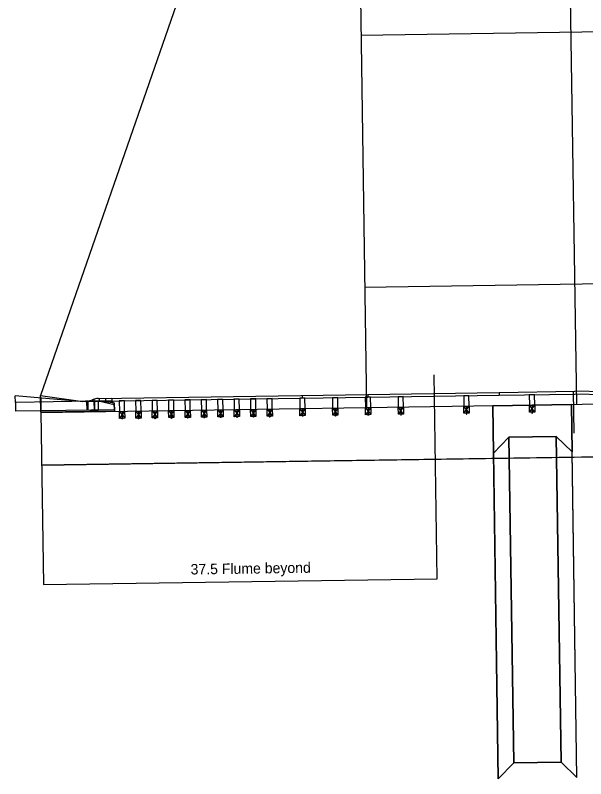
# Model space of a CAD drawing. Extents: x 17498307 to 17498862, y 7167523 to 7167641.
# Drawn here: x 17498671.2 to 17498725.6, y 7167525.4 to 7167598.2 of the extents above; entities that cross this region are included whole.
import ezdxf

# ---------------------------------------------------------------- set-up
doc = ezdxf.new("R2010")
doc.units = 0
for name, color, linetype in [('_CIVIL_CONSTRUCTION', 7, 'Continuous'), ('BridgeSuperStructure', 7, 'Continuous'), ('Default', 7, 'Continuous'), ('Draft_DNC', 7, 'Continuous'), ('dsnCellElements', 7, 'Continuous'), ('TextAlignment', 7, 'Continuous'), ('TL_ForeSlopeBarnRoof', 7, 'Continuous')]:
    doc.layers.add(name, color=color, linetype=linetype)

msp = doc.modelspace()

# ---------------------------------------------------------------- linework, layer by layer
at = {"layer": '_CIVIL_CONSTRUCTION'}
for p, q in [((17498703.967, 7167607.973), (17498704.671, 7167560.765)), ((17498723.964, 7167608.272), (17498724.669, 7167561.067)), ((17498688.995, 7167606.167), (17498673.635, 7167561.932)), ((17498704.142, 7167596.251), (17498754.136, 7167596.997)), ((17498704.5, 7167572.256), (17498754.494, 7167573.003)), ((17498732.925, 7167561.192), (17498673.66, 7167560.296))]:
    msp.add_line(p, q, dxfattribs=at)
at = {"layer": 'BridgeSuperStructure'}
msp.add_line((17498671.219, 7167561.896), (17498671.219, 7167561.896), dxfattribs=at)
at = {"layer": 'Default'}
msp.add_line((17498724.356, 7167562.344), (17498724.419, 7167558.345), dxfattribs=at)
for points in [[(17498680.646, 7167561.245), (17498680.658, 7167560.453), (17498673.659, 7167560.349), (17498673.635, 7167561.932), (17498677.644, 7167561.367), (17498679.644, 7167561.397)], [(17498716.763, 7167556.459), (17498716.696, 7167560.959), (17498724.195, 7167561.071), (17498724.262, 7167556.571), (17498722.74, 7167558.049), (17498718.241, 7167557.981)]]:
    msp.add_lwpolyline(points, close=True, dxfattribs=at)
at = {"layer": 'Draft_DNC'}
for p, q in [((17498711.401, 7167544.493), (17498711.111, 7167563.921)), ((17498673.659, 7167560.349), (17498673.904, 7167543.934)), ((17498732.9, 7167556.191), (17498673.735, 7167555.296)), ((17498673.904, 7167543.934), (17498711.401, 7167544.493))]:
    msp.add_line(p, q, dxfattribs=at)
at = {"layer": 'dsnCellElements'}
for p, q in [((17498671.228, 7167561.282), (17498671.219, 7167561.896)), ((17498677.394, 7167561.374), (17498671.219, 7167561.896)), ((17498679.202, 7167561.672), (17498704.803, 7167562.053)), ((17498698.554, 7167561.96), (17498698.558, 7167561.689)), ((17498704.803, 7167562.053), (17498717.302, 7167562.24)), ((17498704.803, 7167562.053), (17498704.808, 7167561.783)), ((17498704.808, 7167561.783), (17498717.306, 7167561.969)), ((17498708.183, 7167561.833), (17498707.682, 7167561.826)), ((17498708.197, 7167560.832), (17498708.183, 7167561.833)), ((17498714.432, 7167561.926), (17498713.932, 7167561.919)), ((17498713.932, 7167561.919), (17498713.946, 7167560.918)), ((17498714.447, 7167560.926), (17498714.432, 7167561.926)), ((17498717.302, 7167562.24), (17498717.306, 7167561.969)), ((17498678.415, 7167561.389), (17498671.228, 7167561.282)), ((17498671.228, 7167561.282), (17498671.241, 7167560.438)), ((17498673.639, 7167561.691), (17498673.657, 7167560.474)), ((17498678.164, 7167561.411), (17498677.914, 7167561.407)), ((17498677.915, 7167561.382), (17498677.914, 7167561.407)), ((17498677.915, 7167561.382), (17498680.415, 7167561.419)), ((17498678.052, 7167560.54), (17498678.04, 7167561.383)), ((17498678.093, 7167560.593), (17498678.081, 7167561.411)), ((17498678.123, 7167561.385), (17498678.136, 7167560.541)), ((17498679.144, 7167561.4), (17498678.415, 7167561.389)), ((17498678.645, 7167561.57), (17498678.503, 7167561.512)), ((17498678.706, 7167561.393), (17498678.719, 7167560.55)), ((17498678.76, 7167560.603), (17498678.745, 7167561.605)), ((17498678.802, 7167560.551), (17498678.79, 7167561.395)), ((17498679.106, 7167561.67), (17498680.411, 7167561.69)), ((17498680.31, 7167561.417), (17498679.144, 7167561.4)), ((17498680.649, 7167561.047), (17498679.144, 7167561.4)), ((17498679.156, 7167560.556), (17498679.144, 7167561.4)), ((17498679.202, 7167561.672), (17498679.206, 7167561.401)), ((17498679.206, 7167561.401), (17498704.808, 7167561.783)), ((17498679.411, 7167561.405), (17498680.415, 7167561.42)), ((17498679.806, 7167561.681), (17498679.81, 7167561.41)), ((17498680.647, 7167561.172), (17498680.31, 7167561.417)), ((17498680.411, 7167561.69), (17498680.415, 7167561.419)), ((17498680.656, 7167560.578), (17498680.647, 7167561.172)), ((17498681.623, 7167561.435), (17498681.123, 7167561.428)), ((17498681.123, 7167561.428), (17498681.138, 7167560.428)), ((17498681.638, 7167560.436), (17498681.623, 7167561.435)), ((17498683.185, 7167561.458), (17498682.685, 7167561.451)), ((17498682.685, 7167561.451), (17498682.7, 7167560.451)), ((17498683.2, 7167560.459), (17498683.185, 7167561.458)), ((17498684.747, 7167561.482), (17498684.248, 7167561.474)), ((17498684.248, 7167561.474), (17498684.263, 7167560.475)), ((17498684.762, 7167560.482), (17498684.747, 7167561.482)), ((17498686.31, 7167561.505), (17498685.81, 7167561.497)), ((17498685.81, 7167561.497), (17498685.825, 7167560.498)), ((17498686.325, 7167560.506), (17498686.31, 7167561.505)), ((17498687.872, 7167561.528), (17498687.372, 7167561.521)), ((17498687.372, 7167561.521), (17498687.387, 7167560.521)), ((17498687.887, 7167560.529), (17498687.872, 7167561.528)), ((17498689.434, 7167561.552), (17498688.935, 7167561.544)), ((17498688.935, 7167561.544), (17498688.95, 7167560.545)), ((17498689.449, 7167560.552), (17498689.434, 7167561.552)), ((17498690.997, 7167561.575), (17498690.497, 7167561.567)), ((17498690.497, 7167561.567), (17498690.512, 7167560.568)), ((17498691.012, 7167560.576), (17498690.997, 7167561.575)), ((17498692.559, 7167561.598), (17498692.059, 7167561.591)), ((17498692.559, 7167561.598), (17498692.059, 7167561.591)), ((17498692.059, 7167561.591), (17498692.074, 7167560.591)), ((17498692.059, 7167561.591), (17498692.074, 7167560.591)), ((17498692.574, 7167560.599), (17498692.559, 7167561.598)), ((17498692.574, 7167560.599), (17498692.559, 7167561.598)), ((17498694.121, 7167561.622), (17498693.622, 7167561.614)), ((17498693.622, 7167561.614), (17498693.636, 7167560.615)), ((17498694.136, 7167560.622), (17498694.121, 7167561.622)), ((17498695.684, 7167561.645), (17498695.184, 7167561.637)), ((17498695.184, 7167561.637), (17498695.199, 7167560.638)), ((17498695.698, 7167560.645), (17498695.684, 7167561.645)), ((17498698.808, 7167561.692), (17498698.309, 7167561.684)), ((17498698.309, 7167561.684), (17498698.323, 7167560.685)), ((17498698.823, 7167560.692), (17498698.808, 7167561.692)), ((17498701.933, 7167561.738), (17498701.433, 7167561.731)), ((17498701.433, 7167561.731), (17498701.448, 7167560.731)), ((17498701.948, 7167560.739), (17498701.933, 7167561.738)), ((17498705.058, 7167561.785), (17498704.558, 7167561.777)), ((17498704.558, 7167561.777), (17498704.573, 7167560.778)), ((17498705.072, 7167560.785), (17498705.058, 7167561.785)), ((17498707.682, 7167561.826), (17498707.697, 7167560.825)), ((17498678.427, 7167560.545), (17498671.241, 7167560.438)), ((17498679.156, 7167560.556), (17498678.427, 7167560.545)), ((17498680.656, 7167560.578), (17498679.156, 7167560.556)), ((17498681.138, 7167560.428), (17498681.638, 7167560.436)), ((17498681.138, 7167560.428), (17498681.648, 7167559.769)), ((17498681.638, 7167560.436), (17498681.148, 7167559.762)), ((17498681.388, 7167560.432), (17498681.398, 7167559.765)), ((17498682.7, 7167560.451), (17498683.2, 7167560.459)), ((17498682.7, 7167560.451), (17498683.21, 7167559.792)), ((17498683.2, 7167560.459), (17498682.71, 7167559.785)), ((17498682.95, 7167560.455), (17498682.96, 7167559.789)), ((17498684.262, 7167560.475), (17498684.772, 7167559.816)), ((17498684.263, 7167560.475), (17498684.762, 7167560.482)), ((17498684.762, 7167560.482), (17498684.272, 7167559.808)), ((17498684.512, 7167560.479), (17498684.522, 7167559.812)), ((17498685.825, 7167560.498), (17498686.325, 7167560.506)), ((17498685.825, 7167560.498), (17498686.335, 7167559.839)), ((17498686.325, 7167560.506), (17498685.835, 7167559.832)), ((17498686.075, 7167560.502), (17498686.085, 7167559.835)), ((17498687.387, 7167560.521), (17498687.887, 7167560.529)), ((17498687.387, 7167560.521), (17498687.897, 7167559.862)), ((17498687.887, 7167560.529), (17498687.397, 7167559.855)), ((17498687.637, 7167560.525), (17498687.647, 7167559.859)), ((17498688.949, 7167560.545), (17498689.459, 7167559.886)), ((17498688.95, 7167560.545), (17498689.449, 7167560.552)), ((17498689.449, 7167560.552), (17498688.959, 7167559.878)), ((17498689.199, 7167560.548), (17498689.209, 7167559.882)), ((17498690.512, 7167560.568), (17498691.012, 7167560.576)), ((17498690.512, 7167560.568), (17498691.021, 7167559.909)), ((17498691.012, 7167560.576), (17498690.522, 7167559.902)), ((17498690.762, 7167560.572), (17498690.771, 7167559.905)), ((17498692.074, 7167560.591), (17498692.574, 7167560.599)), ((17498692.074, 7167560.591), (17498692.574, 7167560.599)), ((17498692.074, 7167560.591), (17498692.584, 7167559.932)), ((17498692.574, 7167560.599), (17498692.084, 7167559.925)), ((17498692.324, 7167560.595), (17498692.334, 7167559.929)), ((17498693.636, 7167560.615), (17498694.136, 7167560.622)), ((17498693.636, 7167560.615), (17498694.146, 7167559.956)), ((17498694.136, 7167560.622), (17498693.646, 7167559.948)), ((17498693.886, 7167560.618), (17498693.896, 7167559.952)), ((17498695.199, 7167560.638), (17498695.698, 7167560.645)), ((17498695.199, 7167560.638), (17498695.708, 7167559.979)), ((17498695.698, 7167560.645), (17498695.208, 7167559.971)), ((17498695.449, 7167560.642), (17498695.458, 7167559.975)), ((17498698.323, 7167560.685), (17498698.823, 7167560.692)), ((17498698.323, 7167560.685), (17498698.833, 7167560.026)), ((17498698.823, 7167560.692), (17498698.333, 7167560.018)), ((17498698.573, 7167560.688), (17498698.583, 7167560.022)), ((17498701.448, 7167560.731), (17498701.948, 7167560.739)), ((17498701.448, 7167560.731), (17498701.958, 7167560.072)), ((17498701.948, 7167560.739), (17498701.458, 7167560.065)), ((17498701.698, 7167560.735), (17498701.708, 7167560.069)), ((17498704.572, 7167560.778), (17498705.082, 7167560.119)), ((17498704.573, 7167560.778), (17498705.072, 7167560.785)), ((17498705.072, 7167560.785), (17498704.582, 7167560.111)), ((17498704.822, 7167560.782), (17498704.832, 7167560.115)), ((17498707.697, 7167560.825), (17498708.197, 7167560.832)), ((17498708.207, 7167560.166), (17498707.697, 7167560.825)), ((17498707.707, 7167560.158), (17498708.197, 7167560.832)), ((17498707.947, 7167560.829), (17498707.957, 7167560.162)), ((17498713.946, 7167560.918), (17498714.447, 7167560.926)), ((17498714.456, 7167560.259), (17498713.946, 7167560.918)), ((17498713.956, 7167560.252), (17498714.446, 7167560.926)), ((17498714.196, 7167560.922), (17498714.206, 7167560.255)), ((17498724.195, 7167561.071), (17498716.696, 7167560.959)), ((17498717.226, 7167525.445), (17498716.696, 7167560.959)), ((17498724.725, 7167525.557), (17498724.195, 7167561.071)), ((17498681.648, 7167559.769), (17498681.148, 7167559.762)), ((17498681.318, 7167559.764), (17498681.318, 7167559.748)), ((17498681.478, 7167559.75), (17498681.318, 7167559.748)), ((17498681.358, 7167559.748), (17498681.358, 7167559.711)), ((17498681.438, 7167559.712), (17498681.358, 7167559.711)), ((17498681.374, 7167559.748), (17498681.374, 7167559.711)), ((17498681.388, 7167559.711), (17498681.389, 7167559.682)), ((17498681.409, 7167559.682), (17498681.389, 7167559.682)), ((17498681.408, 7167559.712), (17498681.409, 7167559.682)), ((17498681.422, 7167559.749), (17498681.422, 7167559.712)), ((17498681.438, 7167559.749), (17498681.438, 7167559.712)), ((17498681.478, 7167559.767), (17498681.478, 7167559.75)), ((17498683.21, 7167559.792), (17498682.71, 7167559.785)), ((17498682.88, 7167559.787), (17498682.88, 7167559.771)), ((17498683.04, 7167559.773), (17498682.88, 7167559.771)), ((17498682.92, 7167559.772), (17498682.921, 7167559.734)), ((17498683.001, 7167559.735), (17498682.921, 7167559.734)), ((17498682.936, 7167559.772), (17498682.937, 7167559.734)), ((17498682.951, 7167559.735), (17498682.951, 7167559.705)), ((17498682.971, 7167559.705), (17498682.951, 7167559.705)), ((17498682.971, 7167559.735), (17498682.971, 7167559.705)), ((17498682.984, 7167559.772), (17498682.985, 7167559.735)), ((17498683, 7167559.773), (17498683.001, 7167559.735)), ((17498683.04, 7167559.79), (17498683.04, 7167559.773)), ((17498684.772, 7167559.816), (17498684.272, 7167559.808)), ((17498684.442, 7167559.811), (17498684.442, 7167559.794)), ((17498684.602, 7167559.797), (17498684.442, 7167559.794)), ((17498684.482, 7167559.795), (17498684.483, 7167559.757)), ((17498684.563, 7167559.759), (17498684.483, 7167559.757)), ((17498684.498, 7167559.795), (17498684.499, 7167559.758)), ((17498684.513, 7167559.758), (17498684.513, 7167559.728)), ((17498684.533, 7167559.729), (17498684.513, 7167559.728)), ((17498684.533, 7167559.758), (17498684.533, 7167559.729)), ((17498684.546, 7167559.796), (17498684.547, 7167559.758)), ((17498684.562, 7167559.796), (17498684.563, 7167559.759)), ((17498684.602, 7167559.813), (17498684.602, 7167559.797)), ((17498686.335, 7167559.839), (17498685.835, 7167559.832)), ((17498686.005, 7167559.834), (17498686.005, 7167559.818)), ((17498686.165, 7167559.82), (17498686.005, 7167559.818)), ((17498686.045, 7167559.818), (17498686.045, 7167559.781)), ((17498686.125, 7167559.782), (17498686.045, 7167559.781)), ((17498686.061, 7167559.818), (17498686.061, 7167559.781)), ((17498686.075, 7167559.781), (17498686.076, 7167559.752)), ((17498686.096, 7167559.752), (17498686.076, 7167559.752)), ((17498686.095, 7167559.782), (17498686.096, 7167559.752)), ((17498686.109, 7167559.819), (17498686.109, 7167559.782)), ((17498686.125, 7167559.819), (17498686.125, 7167559.782)), ((17498686.165, 7167559.836), (17498686.165, 7167559.82)), ((17498687.897, 7167559.862), (17498687.397, 7167559.855)), ((17498687.567, 7167559.857), (17498687.567, 7167559.841)), ((17498687.727, 7167559.843), (17498687.567, 7167559.841)), ((17498687.607, 7167559.841), (17498687.608, 7167559.804)), ((17498687.688, 7167559.805), (17498687.608, 7167559.804)), ((17498687.623, 7167559.842), (17498687.624, 7167559.804)), ((17498687.638, 7167559.805), (17498687.638, 7167559.775)), ((17498687.658, 7167559.775), (17498687.638, 7167559.775)), ((17498687.658, 7167559.805), (17498687.658, 7167559.775)), ((17498687.671, 7167559.842), (17498687.672, 7167559.805)), ((17498687.687, 7167559.843), (17498687.688, 7167559.805)), ((17498687.727, 7167559.86), (17498687.727, 7167559.843)), ((17498689.459, 7167559.886), (17498688.959, 7167559.878)), ((17498689.129, 7167559.881), (17498689.129, 7167559.864)), ((17498689.289, 7167559.867), (17498689.129, 7167559.864)), ((17498689.169, 7167559.865), (17498689.17, 7167559.827)), ((17498689.25, 7167559.829), (17498689.17, 7167559.827)), ((17498689.185, 7167559.865), (17498689.186, 7167559.828)), ((17498689.2, 7167559.828), (17498689.2, 7167559.798)), ((17498689.22, 7167559.799), (17498689.2, 7167559.798)), ((17498689.22, 7167559.828), (17498689.22, 7167559.799)), ((17498689.233, 7167559.866), (17498689.234, 7167559.828)), ((17498689.249, 7167559.866), (17498689.25, 7167559.829)), ((17498689.289, 7167559.883), (17498689.289, 7167559.867)), ((17498691.021, 7167559.909), (17498690.522, 7167559.902)), ((17498690.692, 7167559.904), (17498690.692, 7167559.888)), ((17498690.852, 7167559.89), (17498690.692, 7167559.888)), ((17498690.732, 7167559.888), (17498690.732, 7167559.851)), ((17498690.812, 7167559.852), (17498690.732, 7167559.851)), ((17498690.748, 7167559.888), (17498690.748, 7167559.851)), ((17498690.762, 7167559.851), (17498690.763, 7167559.822)), ((17498690.783, 7167559.822), (17498690.763, 7167559.822)), ((17498690.782, 7167559.851), (17498690.783, 7167559.822)), ((17498690.796, 7167559.889), (17498690.796, 7167559.852)), ((17498690.812, 7167559.889), (17498690.812, 7167559.852)), ((17498690.851, 7167559.906), (17498690.852, 7167559.89)), ((17498692.584, 7167559.932), (17498692.084, 7167559.925)), ((17498692.254, 7167559.927), (17498692.254, 7167559.911)), ((17498692.414, 7167559.913), (17498692.254, 7167559.911)), ((17498692.294, 7167559.911), (17498692.295, 7167559.874)), ((17498692.375, 7167559.875), (17498692.295, 7167559.874)), ((17498692.31, 7167559.912), (17498692.311, 7167559.874)), ((17498692.325, 7167559.874), (17498692.325, 7167559.845)), ((17498692.345, 7167559.845), (17498692.325, 7167559.845)), ((17498692.345, 7167559.875), (17498692.345, 7167559.845)), ((17498692.358, 7167559.912), (17498692.359, 7167559.875)), ((17498692.374, 7167559.913), (17498692.375, 7167559.875)), ((17498692.414, 7167559.93), (17498692.414, 7167559.913)), ((17498694.146, 7167559.956), (17498693.646, 7167559.948)), ((17498693.816, 7167559.951), (17498693.816, 7167559.934)), ((17498693.976, 7167559.937), (17498693.816, 7167559.934)), ((17498693.856, 7167559.935), (17498693.857, 7167559.897)), ((17498693.937, 7167559.899), (17498693.857, 7167559.897)), ((17498693.872, 7167559.935), (17498693.873, 7167559.898)), ((17498693.887, 7167559.898), (17498693.887, 7167559.868)), ((17498693.907, 7167559.869), (17498693.887, 7167559.868)), ((17498693.907, 7167559.898), (17498693.907, 7167559.869)), ((17498693.92, 7167559.936), (17498693.921, 7167559.898)), ((17498693.936, 7167559.936), (17498693.937, 7167559.899)), ((17498693.976, 7167559.953), (17498693.976, 7167559.937)), ((17498695.708, 7167559.979), (17498695.208, 7167559.971)), ((17498695.378, 7167559.974), (17498695.379, 7167559.957)), ((17498695.539, 7167559.96), (17498695.379, 7167559.957)), ((17498695.419, 7167559.958), (17498695.419, 7167559.921)), ((17498695.499, 7167559.922), (17498695.419, 7167559.921)), ((17498695.435, 7167559.958), (17498695.435, 7167559.921)), ((17498695.449, 7167559.921), (17498695.45, 7167559.892)), ((17498695.47, 7167559.892), (17498695.45, 7167559.892)), ((17498695.469, 7167559.921), (17498695.47, 7167559.892)), ((17498695.483, 7167559.959), (17498695.483, 7167559.922)), ((17498695.499, 7167559.959), (17498695.499, 7167559.922)), ((17498695.538, 7167559.976), (17498695.539, 7167559.96)), ((17498698.833, 7167560.026), (17498698.333, 7167560.018)), ((17498698.503, 7167560.021), (17498698.503, 7167560.004)), ((17498698.663, 7167560.007), (17498698.503, 7167560.004)), ((17498698.543, 7167560.005), (17498698.544, 7167559.967)), ((17498698.624, 7167559.969), (17498698.544, 7167559.967)), ((17498698.559, 7167560.005), (17498698.56, 7167559.968)), ((17498698.574, 7167559.968), (17498698.574, 7167559.938)), ((17498698.594, 7167559.939), (17498698.574, 7167559.938)), ((17498698.594, 7167559.968), (17498698.594, 7167559.939)), ((17498698.607, 7167560.006), (17498698.608, 7167559.968)), ((17498698.623, 7167560.006), (17498698.624, 7167559.969)), ((17498698.663, 7167560.023), (17498698.663, 7167560.007)), ((17498701.958, 7167560.072), (17498701.458, 7167560.065)), ((17498701.628, 7167560.067), (17498701.628, 7167560.051)), ((17498701.788, 7167560.053), (17498701.628, 7167560.051)), ((17498701.668, 7167560.051), (17498701.669, 7167560.014)), ((17498701.749, 7167560.015), (17498701.669, 7167560.014)), ((17498701.684, 7167560.052), (17498701.685, 7167560.014)), ((17498701.699, 7167560.014), (17498701.699, 7167559.985)), ((17498701.719, 7167559.985), (17498701.699, 7167559.985)), ((17498701.719, 7167560.015), (17498701.719, 7167559.985)), ((17498701.732, 7167560.052), (17498701.733, 7167560.015)), ((17498701.748, 7167560.053), (17498701.749, 7167560.015)), ((17498701.788, 7167560.07), (17498701.788, 7167560.053)), ((17498705.082, 7167560.119), (17498704.582, 7167560.111)), ((17498704.752, 7167560.114), (17498704.753, 7167560.097)), ((17498704.913, 7167560.1), (17498704.753, 7167560.097)), ((17498704.793, 7167560.098), (17498704.793, 7167560.061)), ((17498704.873, 7167560.062), (17498704.793, 7167560.061)), ((17498704.809, 7167560.098), (17498704.809, 7167560.061)), ((17498704.823, 7167560.061), (17498704.824, 7167560.032)), ((17498704.844, 7167560.032), (17498704.824, 7167560.032)), ((17498704.843, 7167560.061), (17498704.844, 7167560.032)), ((17498704.857, 7167560.099), (17498704.857, 7167560.062)), ((17498704.873, 7167560.099), (17498704.873, 7167560.062)), ((17498704.912, 7167560.116), (17498704.913, 7167560.1)), ((17498707.959, 7167560.065), (17498707.959, 7167560.058)), ((17498714.208, 7167560.158), (17498714.208, 7167560.151)), ((17498716.763, 7167556.459), (17498718.243, 7167557.983)), ((17498722.74, 7167558.049), (17498718.241, 7167557.981)), ((17498718.704, 7167526.967), (17498718.241, 7167557.981)), ((17498723.203, 7167527.034), (17498722.74, 7167558.049)), ((17498724.262, 7167556.571), (17498722.74, 7167558.049)), ((17498717.226, 7167525.445), (17498718.706, 7167526.969)), ((17498723.203, 7167527.034), (17498718.704, 7167526.967)), ((17498724.725, 7167525.557), (17498723.203, 7167527.034))]:
    msp.add_line(p, q, dxfattribs=at)
for points in [[(17498681.138, 7167560.428), (17498681.638, 7167560.436), (17498681.648, 7167559.769), (17498681.148, 7167559.762)], [(17498682.7, 7167560.451), (17498683.2, 7167560.459), (17498683.21, 7167559.792), (17498682.71, 7167559.785)], [(17498684.262, 7167560.475), (17498684.762, 7167560.482), (17498684.772, 7167559.816), (17498684.272, 7167559.808)], [(17498685.825, 7167560.498), (17498686.325, 7167560.506), (17498686.335, 7167559.839), (17498685.835, 7167559.832)], [(17498687.387, 7167560.521), (17498687.887, 7167560.529), (17498687.897, 7167559.862), (17498687.397, 7167559.855)], [(17498688.949, 7167560.545), (17498689.449, 7167560.552), (17498689.459, 7167559.886), (17498688.959, 7167559.878)], [(17498690.512, 7167560.568), (17498691.012, 7167560.576), (17498691.021, 7167559.909), (17498690.522, 7167559.902)], [(17498692.074, 7167560.591), (17498692.574, 7167560.599), (17498692.584, 7167559.932), (17498692.084, 7167559.925)], [(17498693.636, 7167560.615), (17498694.136, 7167560.622), (17498694.146, 7167559.956), (17498693.646, 7167559.948)], [(17498695.199, 7167560.638), (17498695.698, 7167560.645), (17498695.708, 7167559.979), (17498695.208, 7167559.971)], [(17498698.323, 7167560.685), (17498698.823, 7167560.692), (17498698.833, 7167560.026), (17498698.333, 7167560.018)], [(17498701.448, 7167560.731), (17498701.948, 7167560.739), (17498701.958, 7167560.072), (17498701.458, 7167560.065)], [(17498704.572, 7167560.778), (17498705.072, 7167560.785), (17498705.082, 7167560.119), (17498704.582, 7167560.111)], [(17498707.697, 7167560.825), (17498708.197, 7167560.832), (17498708.207, 7167560.166), (17498707.707, 7167560.158)], [(17498713.946, 7167560.918), (17498714.446, 7167560.926), (17498714.456, 7167560.259), (17498713.956, 7167560.252)]]:
    msp.add_lwpolyline(points, close=True, dxfattribs=at)
for points in [[(17498718.241, 7167557.981), (17498722.74, 7167558.049), (17498724.262, 7167556.571), (17498724.195, 7167561.071), (17498716.696, 7167560.959), (17498716.763, 7167556.459), (17498718.241, 7167557.981)], [(17498707.924, 7167560.161), (17498707.924, 7167560.118), (17498707.991, 7167560.119), (17498707.99, 7167560.162)], [(17498707.938, 7167560.119), (17498707.939, 7167560.064), (17498707.978, 7167560.065), (17498707.977, 7167560.119)], [(17498714.173, 7167560.255), (17498714.174, 7167560.212), (17498714.24, 7167560.213), (17498714.24, 7167560.256)], [(17498714.188, 7167560.212), (17498714.188, 7167560.158), (17498714.227, 7167560.158), (17498714.226, 7167560.213)], [(17498718.241, 7167557.981), (17498716.763, 7167556.459), (17498717.226, 7167525.445), (17498718.704, 7167526.967), (17498718.241, 7167557.981)], [(17498718.704, 7167526.967), (17498723.203, 7167527.034), (17498722.74, 7167558.049), (17498718.241, 7167557.981), (17498718.704, 7167526.967)], [(17498724.725, 7167525.557), (17498724.262, 7167556.571), (17498722.74, 7167558.049), (17498723.203, 7167527.034), (17498724.725, 7167525.557)]]:
    msp.add_lwpolyline(points, dxfattribs=at)
for centre, major_axis, start_param, end_param in [((17498677.933, 7167562.731), (1.379, 0.021), 4.866664, 5.124351), ((17498679.208, 7167560.177), (-1.541, -0.023), 4.763574, 5.071137)]:
    msp.add_ellipse(centre, major_axis=major_axis, ratio=0.97085, start_param=start_param, end_param=end_param, dxfattribs=at)
at = {"layer": 'TextAlignment'}
for p, q in [((17498717.302, 7167562.24), (17498724.527, 7167562.347)), ((17498717.302, 7167562.24), (17498717.306, 7167561.969)), ((17498717.306, 7167561.969), (17498724.529, 7167562.076)), ((17498720.681, 7167562.019), (17498720.181, 7167562.012)), ((17498720.181, 7167562.012), (17498720.196, 7167561.011)), ((17498720.696, 7167561.018), (17498720.681, 7167562.019)), ((17498729.815, 7167562.214), (17498724.527, 7167562.347)), ((17498729.808, 7167561.943), (17498724.529, 7167562.076)), ((17498720.196, 7167561.011), (17498720.696, 7167561.018)), ((17498720.705, 7167560.352), (17498720.196, 7167561.011)), ((17498720.205, 7167560.344), (17498720.696, 7167561.018)), ((17498720.446, 7167561.015), (17498720.455, 7167560.348)), ((17498720.457, 7167560.251), (17498720.457, 7167560.244))]:
    msp.add_line(p, q, dxfattribs=at)
msp.add_lwpolyline([(17498720.196, 7167561.011), (17498720.696, 7167561.018), (17498720.705, 7167560.352), (17498720.205, 7167560.344)], close=True, dxfattribs=at)
for points in [[(17498720.422, 7167560.348), (17498720.423, 7167560.305), (17498720.489, 7167560.306), (17498720.489, 7167560.349)], [(17498720.437, 7167560.305), (17498720.437, 7167560.251), (17498720.476, 7167560.251), (17498720.475, 7167560.305)]]:
    msp.add_lwpolyline(points, dxfattribs=at)
at = {"layer": 'TL_ForeSlopeBarnRoof'}
msp.add_lwpolyline([(17498673.735, 7167555.296), (17498732.9, 7167556.191), (17498732.9, 7167556.191), (17498780.72, 7167554.986), (17498800.817, 7167555.295)], dxfattribs=at)

# ---------------------------------------------------------------- texts
at = {"layer": 'Draft_DNC'}
msp.add_text('37.5 Flume beyond', height=1, rotation=0.85524, dxfattribs=at).set_placement((17498687.929, 7167544.891))

doc.saveas('drawing.dxf')
